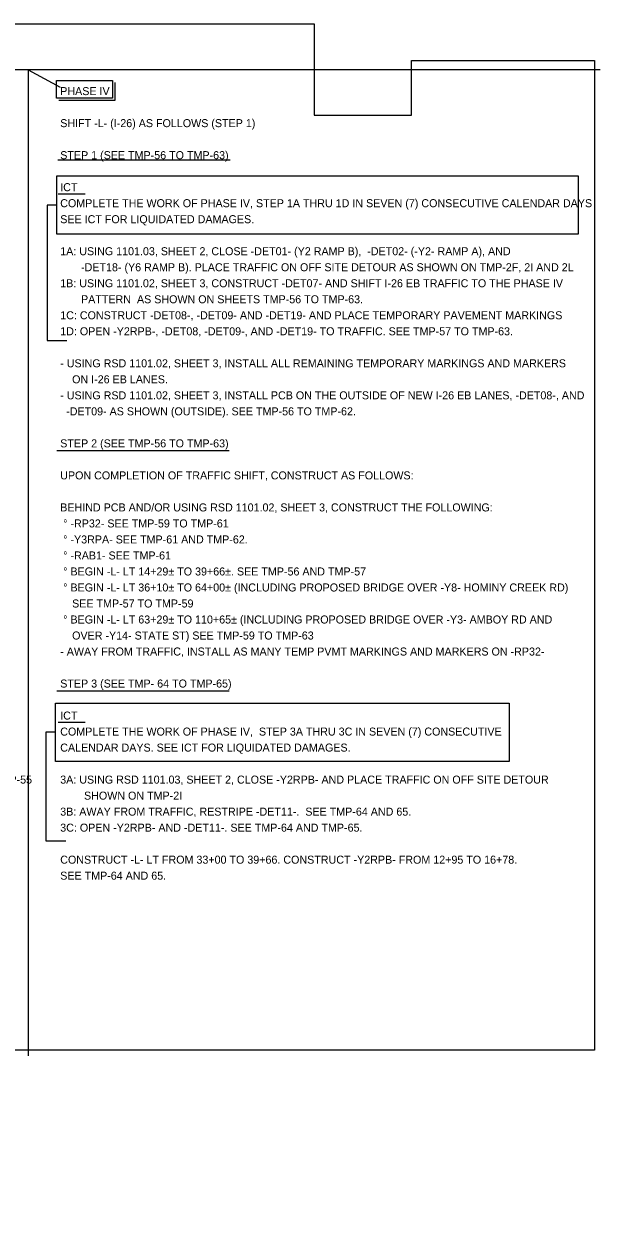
# Model space of a CAD drawing. Extents: x 2483905 to 2494512, y 366160 to 372330.
# Drawn here: x 2492008 to 2492512, y 370218 to 371258 of the extents above; entities that cross this region are included whole.
import ezdxf

# ---------------------------------------------------------------- set-up
doc = ezdxf.new("R2010")
doc.units = 0
for name, color, linetype in [('Scratch_Level_6', 7, 'Continuous'), ('TC SHEET BORDER LINE THIN', 7, 'Continuous'), ('TC SHEET LAYOUT SHAPE', 7, 'Continuous')]:
    doc.layers.add(name, color=color, linetype=linetype)

msp = doc.modelspace()

# ---------------------------------------------------------------- linework, layer by layer
at = {"layer": 'Scratch_Level_6'}
msp.add_line((2492011.6, 371218), (2492039.5, 371202.9), dxfattribs=at)
at = {"layer": 'TC SHEET BORDER LINE THIN'}
for p, q in [((2492511.6, 371218), (2491011.6, 371218)), ((2492011.6, 371218), (2492011.6, 370355.9)), ((2492037.4, 371139.2), (2492188.1, 371139.2)), ((2492037.7, 371109.5), (2492061.3, 371109.5)), ((2492036.5, 371099.8), (2492028, 371099.8)), ((2492028, 371099.8), (2492028, 371099.8)), ((2492028, 371099.8), (2492028, 370981.4)), ((2492028, 370995.6), (2492028, 370995.6)), ((2492028, 370981.4), (2492045.4, 370981.4)), ((2492036.4, 370885.1), (2492187.1, 370885.1)), ((2492036.4, 370675.1), (2492187.1, 370675.1)), ((2492036.4, 370675.1), (2492036.4, 370675.1)), ((2492037.7, 370647.5), (2492061.3, 370647.5)), ((2492035.5, 370638.8), (2492027, 370638.8)), ((2492027, 370638.8), (2492027, 370544)), ((2492027, 370544), (2492044.5, 370544))]:
    msp.add_line(p, q, dxfattribs=at)
for points in [[(2492036.3, 371208.8), (2492085.3, 371208.8), (2492085.3, 371193.1), (2492036.3, 371193.1)], [(2492036.5, 371125.4), (2492492.4, 371125.4), (2492492.4, 371074.3), (2492036.5, 371074.3)], [(2492035.5, 370664.3), (2492432, 370664.3), (2492432, 370613.3), (2492035.5, 370613.3)]]:
    msp.add_lwpolyline(points, close=True, dxfattribs=at)
msp.add_lwpolyline([(2492087.3, 371206.8), (2492087.3, 371191.1), (2492038.3, 371191.1)], dxfattribs=at)
at = {"layer": 'TC SHEET LAYOUT SHAPE'}
msp.add_lwpolyline([(2491016.6, 370666.8), (2491016.6, 370976.2), (2491016.6, 371248.3), (2491026.6, 371258.3), (2491469.6, 371258.3), (2491940.6, 371258.3), (2492261.6, 371258.3), (2492261.6, 371178.3), (2492346.6, 371178.3), (2492346.6, 371226.3), (2492506.6, 371226.3), (2492506.6, 370891.3), (2492506.6, 370612.1), (2492506.6, 370360.8), (2491778.4, 370360.8), (2491778.4, 370218.3), (2491608.9, 370218.3), (2491256.1, 370218.3), (2491016.6, 370218.3)], close=True, dxfattribs=at)

# ---------------------------------------------------------------- texts
at = {"layer": 'TC SHEET BORDER LINE THIN'}
for s, p in [('PHASE IV', (2492039.5, 371195.9)), ('SHIFT -L- (I-26) AS FOLLOWS (STEP 1)', (2492039.5, 371167.9)), ('STEP 1 (SEE TMP-56 TO TMP-63)', (2492039.5, 371139.9)), ('ICT', (2492039.5, 371111.9)), ('COMPLETE THE WORK OF PHASE IV, STEP 1A THRU 1D IN SEVEN (7) CONSECUTIVE CALENDAR DAYS', (2492039.5, 371097.9)), ('SEE ICT FOR LIQUIDATED DAMAGES.', (2492039.5, 371083.9)), ('1A: USING 1101.03, SHEET 2, CLOSE -DET01- (Y2 RAMP B),  -DET02- (-Y2- RAMP A), AND', (2492039.5, 371055.9)), ('       -DET18- (Y6 RAMP B). PLACE TRAFFIC ON OFF SITE DETOUR AS SHOWN ON TMP-2F, 2I AND 2L', (2492039.5, 371041.9)), ('1B: USING 1101.02, SHEET 3, CONSTRUCT -DET07- AND SHIFT I-26 EB TRAFFIC TO THE PHASE IV', (2492039.5, 371027.9)), ('       PATTERN  AS SHOWN ON SHEETS TMP-56 TO TMP-63.', (2492039.5, 371013.9)), ('1C: CONSTRUCT -DET08-, -DET09- AND -DET19- AND PLACE TEMPORARY PAVEMENT MARKINGS', (2492039.5, 370999.9)), ('1D: OPEN -Y2RPB-, -DET08, -DET09-, AND -DET19- TO TRAFFIC. SEE TMP-57 TO TMP-63.', (2492039.5, 370985.9)), ('- USING RSD 1101.02, SHEET 3, INSTALL ALL REMAINING TEMPORARY MARKINGS AND MARKERS', (2492039.5, 370957.9)), ('    ON I-26 EB LANES.', (2492039.5, 370943.9)), ('- USING RSD 1101.02, SHEET 3, INSTALL PCB ON THE OUTSIDE OF NEW I-26 EB LANES, -DET08-, AND', (2492039.5, 370929.9)), ('  -DET09- AS SHOWN (OUTSIDE). SEE TMP-56 TO TMP-62.', (2492039.5, 370915.9)), ('STEP 2 (SEE TMP-56 TO TMP-63)', (2492039.5, 370887.9)), ('UPON COMPLETION OF TRAFFIC SHIFT, CONSTRUCT AS FOLLOWS:', (2492039.5, 370859.9)), ('BEHIND PCB AND/OR USING RSD 1101.02, SHEET 3, CONSTRUCT THE FOLLOWING:', (2492039.5, 370831.9)), (' ° -RP32- SEE TMP-59 TO TMP-61', (2492039.5, 370817.9)), (' ° -Y3RPA- SEE TMP-61 AND TMP-62. ', (2492039.5, 370803.9)), (' ° -RAB1- SEE TMP-61', (2492039.5, 370789.9)), (' ° BEGIN -L- LT 14+29± TO 39+66±. SEE TMP-56 AND TMP-57', (2492039.5, 370775.9)), (' ° BEGIN -L- LT 36+10± TO 64+00± (INCLUDING PROPOSED BRIDGE OVER -Y8- HOMINY CREEK RD)', (2492039.5, 370761.9)), ('    SEE TMP-57 TO TMP-59', (2492039.5, 370747.9)), (' ° BEGIN -L- LT 63+29± TO 110+65± (INCLUDING PROPOSED BRIDGE OVER -Y3- AMBOY RD AND', (2492039.5, 370733.9)), ('    OVER -Y14- STATE ST) SEE TMP-59 TO TMP-63', (2492039.5, 370719.9)), ('- AWAY FROM TRAFFIC, INSTALL AS MANY TEMP PVMT MARKINGS AND MARKERS ON -RP32-', (2492039.5, 370705.9)), ('STEP 3 (SEE TMP- 64 TO TMP-65)', (2492039.5, 370677.9)), ('ICT', (2492039.5, 370649.9)), ('COMPLETE THE WORK OF PHASE IV,  STEP 3A THRU 3C IN SEVEN (7) CONSECUTIVE', (2492039.5, 370635.9)), ('CALENDAR DAYS. SEE ICT FOR LIQUIDATED DAMAGES.', (2492039.5, 370621.9)), ('4D:  SHIFT -L- I-26 WB TRAFFIC TO THE PHASE III, STEP 4 PATTERN AS SHOWN ON TMP-48 THRU TMP-55', (2491539.5, 370593.9)), ('3A: USING RSD 1101.03, SHEET 2, CLOSE -Y2RPB- AND PLACE TRAFFIC ON OFF SITE DETOUR', (2492039.5, 370593.9)), ('        SHOWN ON TMP-2I', (2492039.5, 370579.9)), ('3B: AWAY FROM TRAFFIC, RESTRIPE -DET11-.  SEE TMP-64 AND 65.', (2492039.5, 370565.9)), ('3C: OPEN -Y2RPB- AND -DET11-. SEE TMP-64 AND TMP-65.', (2492039.5, 370551.9)), ('CONSTRUCT -L- LT FROM 33+00 TO 39+66. CONSTRUCT -Y2RPB- FROM 12+95 TO 16+78.', (2492039.5, 370523.9)), ('SEE TMP-64 AND 65.', (2492039.5, 370509.9))]:
    msp.add_text(s, height=7, dxfattribs=at).set_placement(p)

doc.saveas('drawing.dxf')
